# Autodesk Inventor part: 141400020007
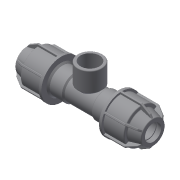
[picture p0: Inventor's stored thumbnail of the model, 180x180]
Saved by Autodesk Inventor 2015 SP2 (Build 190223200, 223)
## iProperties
Created: 2017-08
Part Number: 141400020007
Material: Generic
Description: PLASSON L.14 TEE FEMALE ADAPTOR (SILVER) 20 x 3/4" x 20
Document SubType Name: Modeling
Designer: KIM
Density: 1 g/cm^3
Appearance: Default
Author: KIM
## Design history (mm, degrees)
derived "141400.ipt"
feature "Solid1::141400.ipt"
feature "Solid2::141400.ipt"
tag "TaggingFeature1"
body "Solid1"
other parameters: "d2" = 44, "d4" = 15 deg, "d5" = 29.04, "d6" = 9.5832, "d10" = 42, "d16" = 20.4, "d17" = 2.2, "d22" = 32, "d24" = 2.2, "d25" = 37.8, "d26" = 31.5, "d27" = 2.2, "d28" = 135 deg, "d29" = 1.32, "d31" = 1, "d46" = 150 deg, "d49" = 2.1, "d50" = 0, "d58" = 0.6, "d61" = 360 deg, "d63" = 18, "d64" = 56.5, "d80" = 28.8, "d81" = 1.6, "d84" = 2.2, "d94" = 45, "d95" = 24.117, "d96" = 31.3521, "d97" = 19, "d98" = 18, "d99" = 21.94647, "d100" = 135 deg, "d108" = 1, "d111" = 0, "G_" = 24.117, "E_" = 42, "H_" = 113, "l_" = 44, "l_2" = 19, "A_" = 45
